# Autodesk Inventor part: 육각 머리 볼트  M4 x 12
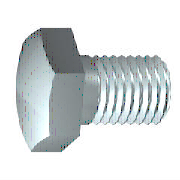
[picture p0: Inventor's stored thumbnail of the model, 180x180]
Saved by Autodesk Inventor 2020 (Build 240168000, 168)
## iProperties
Created: 2012-02
Part Number: 육각 머리 볼트  M4 x 12
Material: 강철, 연강
Description: 6각 머리 나사
Document SubType Name: Modeling
Standard: ISO 4017
Designer: mdu-01
Standard Revision: Third edition 1999-08-15
Standards Organization: ISO
Language: ko-KR
Size Designation: M4 x 12
Categories: <MemberInstance><Categories><Category DisplayName="조임쇠" InternalName="e4da775c-781d-43d5-af7c-5136215cf5a6" Mnemonic="FSTN"><Category DisplayName="볼트" InternalN
Density: 7.75 g/cm^3
Appearance: 강철
IsCustomPart: 1
Author: mdu-01
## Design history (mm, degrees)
sketch "스케치1"
  geometry: L1 (0, 3.015)-(0, 2); L2 (2.1, 2)-(12, 2); L3 (12, 2)-(12, 0); L4 (12, 0)-(-0.4, 0); L5 (-2.88, 0)-(14.48, 0) reference; L6 (-0.4, 0)-(-0.4, 3.015); L7 (-0.4, 3.015)-(0, 3.015); L8 (2.1, 2)-(1.67, 2); L9 (1.67, 2)-(0, 2); L10 (0, -0.603)-(0, 3.618) reference
  constraints: 16 end point, 2 collinear, 2 perpendicular, 1 parallel
  dimensions: "d0" = 12 distance between parallel lines of L3 L1 (= NLG); "d1" = 9.9 distance from line of L2.start L3 (= GEL); "d2" = 4 diameter of L2 L4 (= GD); "d9" = 0.4001 distance between parallel lines of L6 L1 (computed from SD); "d10" = 6.03 diameter of L7 L4 (= SD2); "d13" = 0.42952 distance of L2.start L8.end (computed from GAL); "d14" = 4 diameter of L9 L4 (= BDM)
revolve "본체" sketch "스케치1" stored, may be unused: angle "d12" = 90 deg
sketch "스케치2"
  geometry: L1 (0, 4.041)-(3.5, 2.021); L2 (3.5, 2.021)-(3.5, -2.021); L3 (3.5, -2.021)-(0, -4.041); L4 (0, -4.041)-(-3.5, -2.021); L5 (-3.5, -2.021)-(-3.5, 2.021); L6 (-3.5, 2.021)-(0, 4.041); 2 further points
  constraints: 12 end point, 1 coincident, 1 vertical, 11 other
  dimensions: "d11" = 7 distance between parallel lines of L5 L2 (= SW)
extrude "머리" join sketch "스케치2" distance "d3" = 2.4 (= KOH - SD); taper "d4" = 0 deg
sketch "스케치4"
  geometry: L1 (-2.8, 3.5)-(-2.8, 4.041); L2 (-2.8, 4.041)-(-2.487, 4.041); L3 (-2.487, 4.041)-(-2.8, 3.5); L4 (-3.28, 0)-(0.08, 0) reference; L5 (-0.4, 4.041)-(-2.8, 4.041) reference; L6 (-2.8, 2.021)-(-2.8, 4.041) reference
  constraints: 6 end point, 2 collinear, 1 perpendicular, 1 vertical
  dimensions: "d5" = 30 deg angle of L3 L1 (= ANG1); "d19" = 7 diameter of L1.start L4 (= SW0)
revolve "모따기1" sketch "스케치4" stored, may be unused: angle "d21" = 90 deg
workplane "Work Plane1"
body "Solid1"
feature "스레드" dims "d15" = 9.9 (= GEL), "d16" = 0
chamfer "모따기2" distance "d6" = 0.42941 (= -0.5 x SPD + 0.5 x GD); stored, may be unused: second distance "d7" = 0.42952 (computed from GUL), angle "d55" = 45 deg
other parameters: "NLG" = 12 [user parameter; used in 1 equation term], "GD" = 4 (= NND) [user parameter; used in 2 equation terms], "BDM" = 4 (= NND) [user parameter; used in 1 equation term], "KOH" = 2.8 [user parameter; used in 1 equation term], "GEL" = 9.9 [user parameter; used in 2 equation terms], "SW" = 7 [user parameter; used in 2 equation terms], "SW0" = 7 (= SW) [user parameter; used in 1 equation term], "SPD" = 3.14117 (= NND - 1.2269 x PTC) [user parameter; used in 1 equation term], "SD2" = 6.03 [user parameter; used in 2 equation terms], "SD" = 0.4 [user parameter; used in 2 equation terms], "ANG1" = 30 deg [user parameter; used in 1 equation term], "GAL" = 0.42941 (= 0.61345 x PTC) [user parameter; used in 1 equation term], "GUL" = 0.42941 (= 0.61345 x PTC) [user parameter; used in 1 equation term], "d8" = 0, "RR" = 0.2 [user parameter], "d57" = 0, "d58" = 0, "TPU" = 14.28571 (computed from PTC) [user parameter], "GD1" = 3.14117 (= THREADDIA - 1.2269 x PTC) [user parameter], "THREADDIA" = 4 [user parameter; used in 1 equation term], "SDH" = 6.03 (= SD2) [user parameter], "SDHG" = 2.1 [user parameter], "TOA" = 30 deg [user parameter], "PTC" = 0.7 [user parameter; used in 5 equation terms], "NND" = 4 [user parameter; used in 3 equation terms], "E0" = 8.085 [user parameter]
